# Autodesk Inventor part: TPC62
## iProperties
Shininess: 64.0
Length Units: 11272
Angle Units: 11279
Time Units: 11290
Mass Units: 11286
Length Display Precision: 3
Angle Display Precision: 2
Compacted: True
Part Number: TPC62
Document SubType Name: Modeling
Created: 2004-08
Designer: Lori
Manufacturer: Standard
Standards Organization: Custom
Density: 0.0
Volumn: 0.0
Area: 0.0
PropertySet Name: Model Information
Control State: 0
Master: False
Checked Out: False
Author: Lori
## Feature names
1. Base1
